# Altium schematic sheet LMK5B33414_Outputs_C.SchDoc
size C; Date: Not shown in title block; ApprovedBy: Not shown in title block; CheckedBy: Not shown in title block; Author: Not shown in title block; CompanyName: Not shown in title block; Engineer: Not shown in title block; Organization: Not shown in title block; Address1: Not shown in title block; Address2: Not shown in title block; Address3: Not shown in title block; Address4: Not shown in title block; DocumentNumber: 2; Revision: Use project parameter SCH_Rev; SheetNumber: 2; SheetTotal: 3; PageSetup: Record=PageOptions¦CenterHorizontal=True¦CenterVertical=True¦PrintScale=1.00¦XCorrection=1.00¦YCorrection=1.00¦PrintKind=0¦BorderSize=5000000¦LeftOffset=0¦BottomOffset=0¦Orientation=2¦PaperLength=1000¦PaperWidth=1000¦Scale=100¦PaperSource=15¦PrintQuality=600¦MediaType=1¦DitherType=10¦PaperKind=Letter¦PrintScaleMode=1
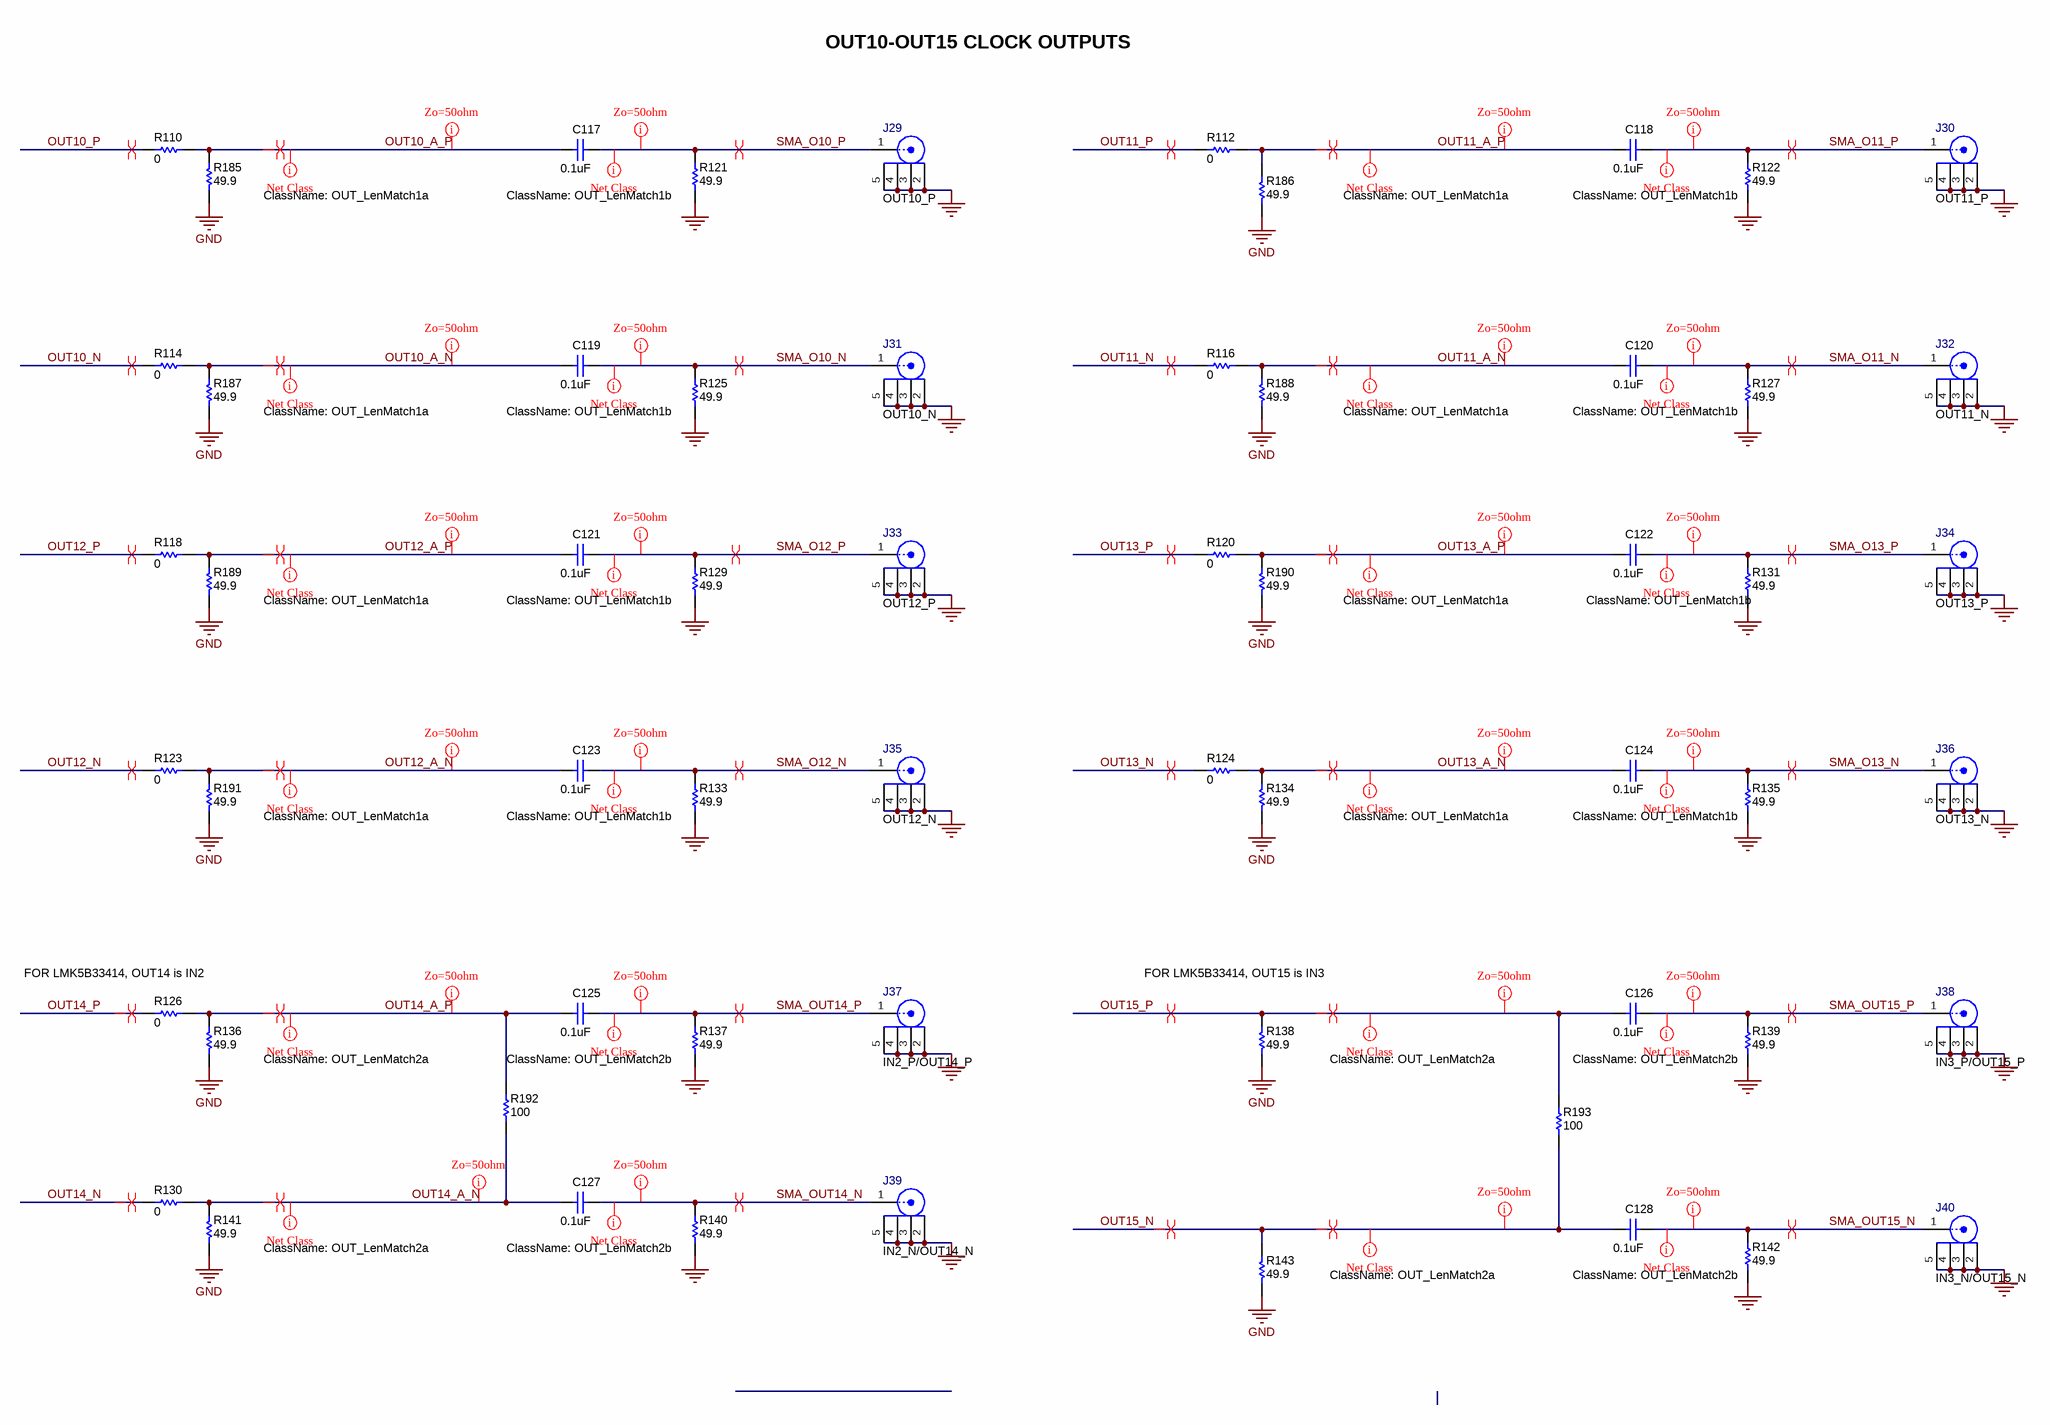
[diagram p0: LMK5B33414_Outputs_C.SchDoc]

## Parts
C117  ValueDisplayed: 0.1uF  [0402L]  (hidden comment: GRM155R71E104KE14D)
C118  ValueDisplayed: 0.1uF  [0402L]  (hidden comment: GRM155R71E104KE14D)
C119  ValueDisplayed: 0.1uF  [0402L]  (hidden comment: GRM155R71E104KE14D)
C120  ValueDisplayed: 0.1uF  [0402L]  (hidden comment: GRM155R71E104KE14D)
C121  ValueDisplayed: 0.1uF  [0402L]  (hidden comment: GRM155R71E104KE14D)
C122  ValueDisplayed: 0.1uF  [0402L]  (hidden comment: GRM155R71E104KE14D)
C123  ValueDisplayed: 0.1uF  [0402L]  (hidden comment: GRM155R71E104KE14D)
C124  ValueDisplayed: 0.1uF  [0402L]  (hidden comment: GRM155R71E104KE14D)
C125  ValueDisplayed: 0.1uF  [0402L]  (hidden comment: GRM155R71E104KE14D)
C126  ValueDisplayed: 0.1uF  [0402L]  (hidden comment: GRM155R71E104KE14D)
C127  ValueDisplayed: 0.1uF  [0402L]  (hidden comment: GRM155R71E104KE14D)
C128  ValueDisplayed: 0.1uF  [0402L]  (hidden comment: GRM155R71E104KE14D)
J29  OUT10_P  [FP-CON-SMA-EDGE-S_CONN_JACK-MFG]
J30  OUT11_P  [FP-CON-SMA-EDGE-S_CONN_JACK-MFG]
J31  OUT10_N  [FP-CON-SMA-EDGE-S_CONN_JACK-MFG]
J32  OUT11_N  [FP-CON-SMA-EDGE-S_CONN_JACK-MFG]
J33  OUT12_P  [FP-CON-SMA-EDGE-S_CONN_JACK-MFG]
J34  OUT13_P  [FP-CON-SMA-EDGE-S_CONN_JACK-MFG]
J35  OUT12_N  [FP-CON-SMA-EDGE-S_CONN_JACK-MFG]
J36  OUT13_N  [FP-CON-SMA-EDGE-S_CONN_JACK-MFG]
J37  IN2_P/OUT14_P  [FP-CON-SMA-EDGE-S_CONN_JACK-MFG]
J38  IN3_P/OUT15_P  [FP-CON-SMA-EDGE-S_CONN_JACK-MFG]
J39  IN2_N/OUT14_N  [FP-CON-SMA-EDGE-S_CONN_JACK-MFG]
J40  IN3_N/OUT15_N  [FP-CON-SMA-EDGE-S_CONN_JACK-MFG]
R110  ValueDisplayed: 0  [0402L]  (hidden comment: RK73Z1ETTP)
R112  ValueDisplayed: 0  [0402L]  (hidden comment: RK73Z1ETTP)
R114  ValueDisplayed: 0  [0402L]  (hidden comment: RK73Z1ETTP)
R116  ValueDisplayed: 0  [0402L]  (hidden comment: RK73Z1ETTP)
R118  ValueDisplayed: 0  [0402L]  (hidden comment: RK73Z1ETTP)
R120  ValueDisplayed: 0  [0402L]  (hidden comment: RK73Z1ETTP)
R121  ValueDisplayed: 49.9  [0402S]  (hidden comment: ERJ-2RKF49R9X)
R122  ValueDisplayed: 49.9  [0402S]  (hidden comment: ERJ-2RKF49R9X)
R123  ValueDisplayed: 0  [0402L]  (hidden comment: RK73Z1ETTP)
R124  ValueDisplayed: 0  [0402L]  (hidden comment: RK73Z1ETTP)
R125  ValueDisplayed: 49.9  [0402S]  (hidden comment: ERJ-2RKF49R9X)
R126  ValueDisplayed: 0  [0402L]  (hidden comment: RK73Z1ETTP)
R127  ValueDisplayed: 49.9  [0402S]  (hidden comment: ERJ-2RKF49R9X)
R129  ValueDisplayed: 49.9  [0402S]  (hidden comment: ERJ-2RKF49R9X)
R130  ValueDisplayed: 0  [0402L]  (hidden comment: RK73Z1ETTP)
R131  ValueDisplayed: 49.9  [0402S]  (hidden comment: ERJ-2RKF49R9X)
R133  ValueDisplayed: 49.9  [0402S]  (hidden comment: ERJ-2RKF49R9X)
R134  ValueDisplayed: 49.9  [0402S]  (hidden comment: ERJ-2RKF49R9X)
R135  ValueDisplayed: 49.9  [0402S]  (hidden comment: ERJ-2RKF49R9X)
R136  ValueDisplayed: 49.9  [0402S]  (hidden comment: ERJ-2RKF49R9X)
R137  ValueDisplayed: 49.9  [0402S]  (hidden comment: ERJ-2RKF49R9X)
R138  ValueDisplayed: 49.9  [0402S]  (hidden comment: ERJ-2RKF49R9X)
R139  ValueDisplayed: 49.9  [0402S]  (hidden comment: ERJ-2RKF49R9X)
R140  ValueDisplayed: 49.9  [0402S]  (hidden comment: ERJ-2RKF49R9X)
R141  ValueDisplayed: 49.9  [0402S]  (hidden comment: ERJ-2RKF49R9X)
R142  ValueDisplayed: 49.9  [0402S]  (hidden comment: ERJ-2RKF49R9X)
R143  ValueDisplayed: 49.9  [0402S]  (hidden comment: ERJ-2RKF49R9X)
R185  ValueDisplayed: 49.9  [0402S]  (hidden comment: ERJ-2RKF49R9X)
R186  ValueDisplayed: 49.9  [0402S]  (hidden comment: ERJ-2RKF49R9X)
R187  ValueDisplayed: 49.9  [0402S]  (hidden comment: ERJ-2RKF49R9X)
R188  ValueDisplayed: 49.9  [0402S]  (hidden comment: ERJ-2RKF49R9X)
R189  ValueDisplayed: 49.9  [0402S]  (hidden comment: ERJ-2RKF49R9X)
R190  ValueDisplayed: 49.9  [0402S]  (hidden comment: ERJ-2RKF49R9X)
R191  ValueDisplayed: 49.9  [0402S]  (hidden comment: ERJ-2RKF49R9X)
R192  ValueDisplayed: 100  [0402L]  (hidden comment: CRCW0402100RFKED)
R193  ValueDisplayed: 100  [0402L]  (hidden comment: CRCW0402100RFKED)

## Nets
GND: J29.2 J29.3 J29.4 J29.5 J30.2 J30.3 J30.4 J30.5 J31.2 J31.3 J31.4 J31.5 J32.2 J32.3 J32.4 J32.5 J33.2 J33.3 J33.4 J33.5 J34.2 J34.3 J34.4 J34.5 J35.2 J35.3 J35.4 J35.5 J36.2 J36.3 J36.4 J36.5 J37.2 J37.3 J37.4 J37.5 J38.2 J38.3 J38.4 J38.5 J39.2 J39.3 J39.4 J39.5 J40.2 J40.3 J40.4 J40.5 R121.1 R122.1 R125.1 R127.1 R129.1 R131.1 R133.1 R134.2 R135.1 R136.2 R137.1 R138.2 R139.1 R140.1 R141.2 R142.1 R143.2 R185.2 R186.2 R187.2 R188.2 R189.2 R190.2 R191.2
OUT10_A_N: C119.2 R114.2 R187.1
OUT10_A_P: C117.2 R110.2 R185.1
OUT10_N: R114.1
OUT10_P: R110.1
OUT11_A_N: C120.2 R116.2 R188.1
OUT11_A_P: C118.2 R112.2 R186.1
OUT11_N: R116.1
OUT11_P: R112.1
OUT12_A_N: C123.2 R123.2 R191.1
OUT12_A_P: C121.2 R118.2 R189.1
OUT12_N: R123.1
OUT12_P: R118.1
OUT13_A_N: C124.2 R124.2 R134.1
OUT13_A_P: C122.2 R120.2 R190.1
OUT13_N: R124.1
OUT13_P: R120.1
OUT14_A_N: C127.2 R130.2 R141.1 R192.1
OUT14_A_P: C125.2 R126.2 R136.1 R192.2
OUT14_N: R130.1
OUT14_P: R126.1
OUT15_N: C128.2 R143.1 R193.1
OUT15_P: C126.2 R138.1 R193.2
SMA_O10_N: C119.1 J31.1 R125.2
SMA_O10_P: C117.1 J29.1 R121.2
SMA_O11_N: C120.1 J32.1 R127.2
SMA_O11_P: C118.1 J30.1 R122.2
SMA_O12_N: C123.1 J35.1 R133.2
SMA_O12_P: C121.1 J33.1 R129.2
SMA_O13_N: C124.1 J36.1 R135.2
SMA_O13_P: C122.1 J34.1 R131.2
SMA_OUT14_N: C127.1 J39.1 R140.2
SMA_OUT14_P: C125.1 J37.1 R137.2
SMA_OUT15_N: C128.1 J40.1 R142.2
SMA_OUT15_P: C126.1 J38.1 R139.2

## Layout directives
rule Impedance Constraint [Min = 45.00    Max = 55.00    ]: OUT10_A_N, OUT10_A_P, OUT11_A_N, OUT11_A_P, OUT12_A_N, OUT12_A_P, OUT13_A_N, OUT13_A_P, OUT14_A_N, OUT14_A_P, OUT15_N, OUT15_P, SMA_O10_N, SMA_O10_P, SMA_O11_N, SMA_O11_P, SMA_O12_N, SMA_O12_P, SMA_O13_N, SMA_O13_P, SMA_OUT14_N, SMA_OUT14_P, SMA_OUT15_N, SMA_OUT15_P
differential pair: OUT10_A_N, OUT10_A_P, OUT10_N, OUT10_P, OUT11_A_N, OUT11_A_P, OUT11_N, OUT11_P, OUT12_A_N, OUT12_A_P, OUT12_N, OUT12_P, OUT13_A_N, OUT13_A_P, OUT13_N, OUT13_P, OUT14_A_N, OUT14_A_P, OUT14_N, OUT14_P, OUT15_N, OUT15_P, SMA_O10_N, SMA_O10_P, SMA_O11_N, SMA_O11_P, SMA_O12_N, SMA_O12_P, SMA_O13_N, SMA_O13_P, SMA_OUT14_N, SMA_OUT14_P, SMA_OUT15_N, SMA_OUT15_P
net class OUT_LenMatch1a: OUT10_A_N, OUT10_A_P, OUT11_A_N, OUT11_A_P, OUT12_A_N, OUT12_A_P, OUT13_A_N, OUT13_A_P
net class OUT_LenMatch2a: OUT14_A_N, OUT14_A_P, OUT15_N, OUT15_P
net class OUT_LenMatch2b: SMA_OUT14_N, SMA_OUT14_P, SMA_OUT15_N, SMA_OUT15_P
net class OUT_LenMatch1b: SMA_O10_N, SMA_O10_P, SMA_O11_N, SMA_O11_P, SMA_O12_N, SMA_O12_P, SMA_O13_N, SMA_O13_P

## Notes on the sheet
- OUT10-OUT15 CLOCK OUTPUTS
- FOR LMK5B33414, OUT14 is IN2
- (near R138) FOR LMK5B33414, OUT15 is IN3

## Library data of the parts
C117-C128 = CMP-0006659-2: CAP, CERM, 0.1 uF, 25 V, +/- 10%, X7R, 0402; Manufacturer: MuRata; TaMin_C: -55°C; Polarized: N; SizeAreaWB_mm2: 3; Value1: Unknown; U/M: EA; Value: 0.1uF; TaMax_C: 125°C; SizeZ_mm: 0.6; SizeX_mm: 1; SizeY_mm: 0.5; Cap_Case: 0402; Value2: 25V; CompType: Capacitor; Cap_F: 100nF; AEC Category: Q200
J29-J40 = CMP-0088000-4: CONN SMA JACK STR EDGE MNT; Manufacturer: RF Solutions Ltd.; PartNumber: CON-SMA-EDGE-S; ContactFinish: Gold; Shrouded: true
R110 R112 R114 R116 R118 R120 R123 R124 R126 R130 = CMP-0027007-2: RES, 0, 5%, 0.063 W, AEC-Q200 Grade 0, 0402; Manufacturer: KOA Speer; Power_W: 63mW; TempCo: ppm/C; Value_Code: 0000; U/M: EA; Value: 0; EIA_Code: E24; SizeX_mm: 1; SizeY_mm: 0.5; SizeZ_mm: 0.6; Value2: 0.063W; CompType: Resistor; AEC Qualified: Y; AEC Category: Q200
R121 R122 R125 R127 R129 R131 R133 R135 R137 R139 R140 R142 = CMP-0026703-1: RES, 49.9, 1%, 0.1 W, AEC-Q200 Grade 0, 0402; Manufacturer: Panasonic; Value: 49.9; Value_Code: 49R9; Power_W: 100mW; Value2: 0.1W; VDC_V: 50V; TempCo: 100 ppm/C; EIA_Code: E96; SizeArea_mm2: 0.5; SizeX_mm: 1; SizeZ_mm: 0.6; AEC Category: Q200; AEC Qualified: Y; AEC Grade: 0; U/M: EA
R134 R136 R138 R141 R143 R185-R191 = CMP-0026703-1: RES, 49.9, 1%, 0.1 W, AEC-Q200 Grade 0, 0402; Manufacturer: Panasonic; Power_W: 100mW; TempCo: 100 ppm/C; Value_Code: 49R9; Value: 49.9; EIA_Code: E96; SizeX_mm: 1; SizeY_mm: 0.5; SizeZ_mm: 0.6; Value2: 0.1W; AEC Qualified: Y; VDC_V: 50V; AEC Category: Q200; AEC Grade: 0; U/M: EA
R192 R193 = CMP-0025951-3: RES, 100, 1%, 0.063 W, AEC-Q200 Grade 0, 0402; Manufacturer: Vishay-Dale; CompType: Resistor; Value: 100; Value_Code: 100R; Power_W: 63mW; Value2: 0.063W; VDC_V: 50V; TempCo: 100 ppm/C; EIA_Code: E96; AEC Category: Q200; AEC Qualified: Y; AEC Grade: 0; SizeArea_mm2: 0.5; SizeX_mm: 1; SizeZ_mm: 0.6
